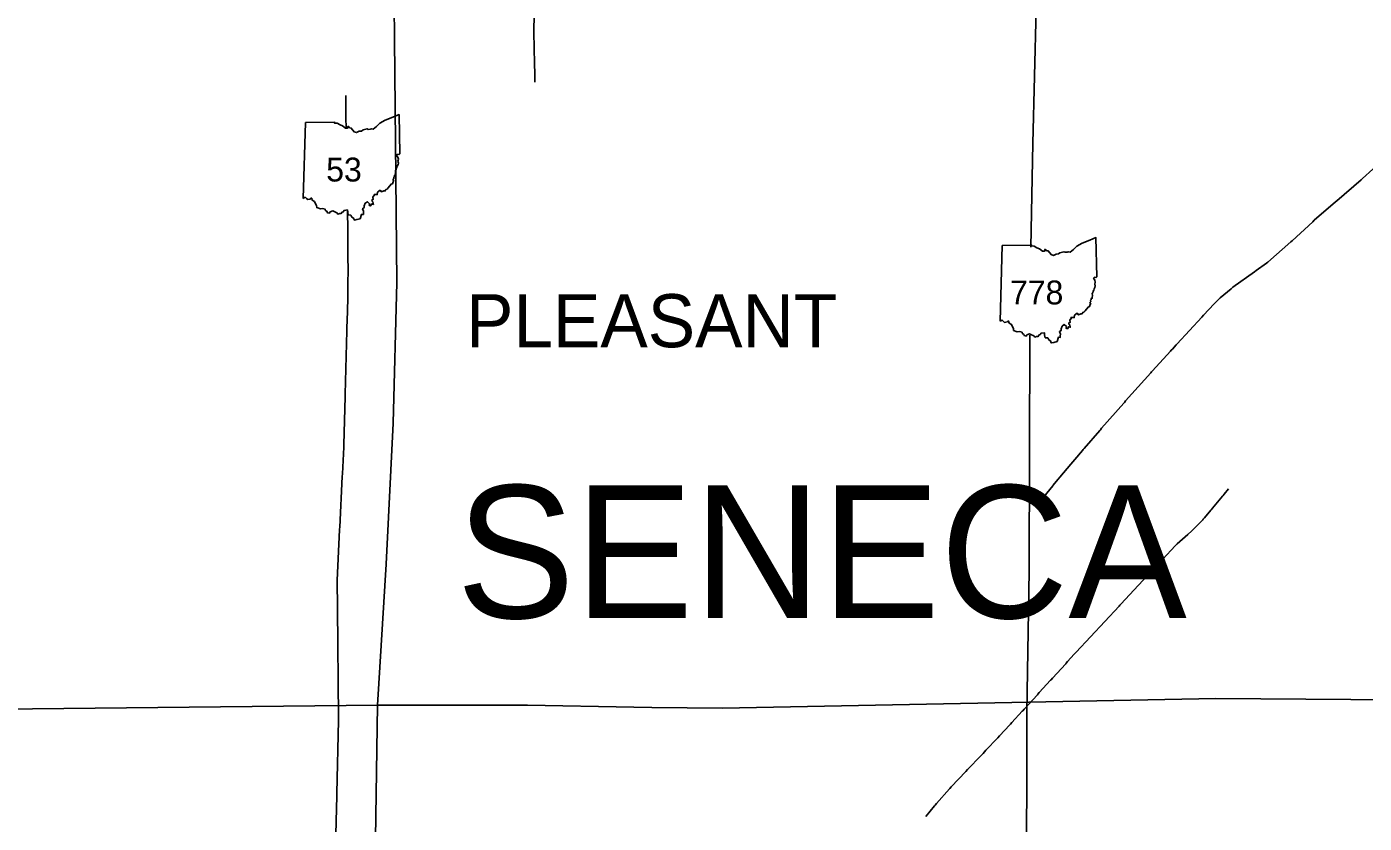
# Model space of a CAD drawing. Extents: x -232 to 448, y 619 to 1059.
# Drawn here: x 257.8 to 309.5, y 743.5 to 774.3 of the extents above; entities that cross this region are included whole.
import ezdxf

# ---------------------------------------------------------------- set-up
doc = ezdxf.new("R2010")
doc.units = 0
doc.layers.add('Default', color=7, linetype='Continuous')

msp = doc.modelspace()

# ---------------------------------------------------------------- linework, layer by layer
at = {"layer": 'Default'}
for p, q in [((268.493, 767.694), (268.575, 770.623)), ((268.493, 767.694), (268.575, 770.623)), ((295.404, 762.944), (295.485, 765.873)), ((295.404, 762.944), (295.485, 765.873))]:
    msp.add_line(p, q, dxfattribs=at)
for points in [[(277.435, 772.188), (277.432, 772.446), (277.422, 772.97), (277.413, 773.432), (277.399, 774.19), (277.413, 774.769), (277.424, 775.181), (277.447, 775.716), (277.475, 776.402), (277.501, 776.941), (277.52, 777.383), (277.539, 777.843), (277.555, 778.261), (277.567, 778.607), (277.572, 779.098), (277.583, 779.571), (277.604, 780.06), (277.627, 780.618), (277.635, 780.905)], [(296.593, 765.811), (296.668, 769.813), (296.793, 775.026), (297.049, 780.749)], [(271.364, 748.108), (271.69, 753.559), (271.965, 759.004), (272.104, 764.439), (272.061, 769.867), (271.962, 779.188)], [(270.145, 770.404), (270.145, 770.418), (270.142, 770.81), (270.137, 771.343), (270.133, 771.671)], [(268.575, 770.623), (269.712, 770.642), (269.694, 770.606), (269.801, 770.599), (269.915, 770.536), (270.012, 770.497), (270.129, 770.404), (270.2, 770.405), (270.23, 770.481), (270.284, 770.422), (270.348, 770.412), (270.459, 770.272), (270.55, 770.241), (270.659, 770.289), (270.741, 770.297), (270.801, 770.345), (270.957, 770.385), (271.001, 770.361), (271.083, 770.366), (271.125, 770.384), (271.197, 770.368), (271.324, 770.474), (271.454, 770.6), (271.655, 770.718), (271.954, 770.831), (272.192, 770.931), (272.226, 769.411)], [(268.575, 770.623), (269.712, 770.642), (269.694, 770.606), (269.801, 770.599), (269.915, 770.536), (270.012, 770.497), (270.129, 770.404), (270.2, 770.405), (270.23, 770.481), (270.284, 770.422), (270.348, 770.412), (270.459, 770.272), (270.55, 770.241), (270.659, 770.289), (270.741, 770.297), (270.801, 770.345), (270.957, 770.385), (271.001, 770.361), (271.083, 770.366), (271.125, 770.384), (271.197, 770.368), (271.324, 770.474), (271.454, 770.6), (271.655, 770.718), (271.954, 770.831), (272.192, 770.931), (272.226, 769.411)], [(272.226, 769.411), (272.191, 769.39), (272.136, 769.4), (272.1, 769.357), (272.145, 769.286), (272.166, 769.211), (272.147, 769.128), (272.166, 769.06), (272.153, 769.002), (272.119, 768.946), (272.107, 768.891), (272.078, 768.834), (272.081, 768.802), (272.053, 768.777), (272.058, 768.682), (272.044, 768.629), (272.049, 768.584), (272.004, 768.572), (272.014, 768.534), (271.986, 768.505), (271.992, 768.455), (271.959, 768.423), (271.991, 768.36), (271.965, 768.339), (271.944, 768.262), (271.887, 768.246), (271.771, 768.104), (271.73, 768.051), (271.684, 768.037), (271.659, 767.982), (271.603, 767.982), (271.517, 767.944), (271.462, 768.01), (271.366, 767.931), (271.354, 767.839), (271.232, 767.842), (271.237, 767.796), (271.21, 767.782), (271.185, 767.736), (271.199, 767.654), (271.142, 767.633), (271.149, 767.585), (271.186, 767.556), (271.202, 767.465), (271.141, 767.483), (271.091, 767.407), (271.04, 767.425), (271.057, 767.49), (270.97, 767.568), (270.888, 767.505), (270.846, 767.405), (270.845, 767.338), (270.784, 767.297), (270.823, 767.202), (270.816, 767.136), (270.817, 767.074), (270.741, 767.076), (270.695, 766.908)], [(272.226, 769.411), (272.191, 769.39), (272.136, 769.4), (272.1, 769.357), (272.145, 769.286), (272.166, 769.211), (272.147, 769.128), (272.166, 769.06), (272.153, 769.002), (272.119, 768.946), (272.107, 768.891), (272.078, 768.834), (272.081, 768.802), (272.053, 768.777), (272.058, 768.682), (272.044, 768.629), (272.049, 768.584), (272.004, 768.572), (272.014, 768.534), (271.986, 768.505), (271.992, 768.455), (271.959, 768.423), (271.991, 768.36), (271.965, 768.339), (271.944, 768.262), (271.887, 768.246), (271.771, 768.104), (271.73, 768.051), (271.684, 768.037), (271.659, 767.982), (271.603, 767.982), (271.517, 767.944), (271.462, 768.01), (271.366, 767.931), (271.354, 767.839), (271.232, 767.842), (271.237, 767.796), (271.21, 767.782), (271.185, 767.736), (271.199, 767.654), (271.142, 767.633), (271.149, 767.585), (271.186, 767.556), (271.202, 767.465), (271.141, 767.483), (271.091, 767.407), (271.04, 767.425), (271.057, 767.49), (270.97, 767.568), (270.888, 767.505), (270.846, 767.405), (270.845, 767.338), (270.784, 767.297), (270.823, 767.202), (270.816, 767.136), (270.817, 767.074), (270.741, 767.076), (270.695, 766.908)], [(296.922, 755.957), (297.432, 756.587), (297.455, 756.616), (297.501, 756.67), (297.85, 757.082), (297.867, 757.101), (297.92, 757.164), (298.582, 757.948), (298.613, 757.985), (298.652, 758.031), (299.251, 758.726), (299.275, 758.754), (299.322, 758.808), (300.177, 759.783), (300.201, 759.811), (300.248, 759.864), (301.217, 760.954), (301.245, 760.985), (301.29, 761.034), (301.981, 761.793), (302.008, 761.823), (302.054, 761.873), (302.199, 762.032), (302.236, 762.073), (303.19, 763.109), (303.262, 763.187), (303.667, 763.624), (303.704, 763.664), (303.861, 763.813), (303.904, 763.853), (304.318, 764.202), (304.318, 764.202), (304.389, 764.262), (305.23, 764.857), (305.296, 764.904), (305.69, 765.191), (305.736, 765.225), (306.632, 766.01), (306.684, 766.055), (307.475, 766.795), (307.531, 766.847), (308.349, 767.557), (308.399, 767.6), (309.338, 768.418), (309.392, 768.465), (310.198, 769.189)], [(270.695, 766.908), (270.562, 766.876), (270.47, 766.856), (270.438, 766.933), (270.372, 766.973), (270.329, 767.05), (270.234, 767.061), (270.212, 767.166), (270.201, 767.252), (270.072, 767.231), (270.037, 767.178), (269.991, 767.164), (269.964, 767.111), (269.902, 767.107), (269.835, 767.082), (269.791, 767.134), (269.681, 767.186), (269.632, 767.213), (269.528, 767.171), (269.506, 767.122), (269.424, 767.143), (269.405, 767.198), (269.355, 767.215), (269.344, 767.273), (269.238, 767.304), (269.156, 767.292), (269.013, 767.339), (269.004, 767.416), (268.955, 767.509), (268.93, 767.574), (268.839, 767.624), (268.821, 767.701), (268.792, 767.699), (268.765, 767.667), (268.665, 767.653), (268.624, 767.685), (268.568, 767.738), (268.493, 767.694)], [(270.695, 766.908), (270.562, 766.876), (270.47, 766.856), (270.438, 766.933), (270.372, 766.973), (270.329, 767.05), (270.234, 767.061), (270.212, 767.166), (270.201, 767.252), (270.072, 767.231), (270.037, 767.178), (269.991, 767.164), (269.964, 767.111), (269.902, 767.107), (269.835, 767.082), (269.791, 767.134), (269.681, 767.186), (269.632, 767.213), (269.528, 767.171), (269.506, 767.122), (269.424, 767.143), (269.405, 767.198), (269.355, 767.215), (269.344, 767.273), (269.238, 767.304), (269.156, 767.292), (269.013, 767.339), (269.004, 767.416), (268.955, 767.509), (268.93, 767.574), (268.839, 767.624), (268.821, 767.701), (268.792, 767.699), (268.765, 767.667), (268.665, 767.653), (268.624, 767.685), (268.568, 767.738), (268.493, 767.694)], [(269.71, 741.633), (269.793, 744.604), (269.793, 744.612), (269.795, 744.712), (269.852, 747.521), (269.853, 747.576), (269.852, 747.63), (269.812, 751.854), (269.812, 751.873), (269.811, 751.963), (269.806, 752.829), (269.806, 752.871), (269.809, 752.937), (269.897, 754.885), (269.898, 754.916), (269.902, 754.993), (269.998, 756.941), (269.998, 756.944), (270.004, 757.049), (270.063, 758.077), (270.063, 758.079), (270.065, 758.185), (270.109, 760.026), (270.109, 760.042), (270.111, 760.134), (270.173, 762.571), (270.174, 762.597), (270.176, 762.679), (270.197, 763.329), (270.198, 763.332), (270.201, 763.437), (270.213, 763.762), (270.215, 763.816), (270.216, 764.039), (270.219, 764.408), (270.222, 764.916), (270.221, 765.449), (270.217, 766.003), (270.21, 766.605), (270.202, 767.09), (270.199, 767.251)], [(295.485, 765.873), (296.622, 765.892), (296.604, 765.857), (296.711, 765.849), (296.825, 765.787), (296.922, 765.747), (297.039, 765.654), (297.11, 765.655), (297.14, 765.731), (297.194, 765.672), (297.258, 765.662), (297.369, 765.522), (297.46, 765.491), (297.57, 765.539), (297.651, 765.547), (297.711, 765.595), (297.867, 765.635), (297.911, 765.611), (297.993, 765.616), (298.035, 765.634), (298.107, 765.618), (298.234, 765.724), (298.364, 765.85), (298.565, 765.969), (298.865, 766.081), (299.102, 766.181), (299.136, 764.661)], [(295.485, 765.873), (296.622, 765.892), (296.604, 765.857), (296.711, 765.849), (296.825, 765.787), (296.922, 765.747), (297.039, 765.654), (297.11, 765.655), (297.14, 765.731), (297.194, 765.672), (297.258, 765.662), (297.369, 765.522), (297.46, 765.491), (297.57, 765.539), (297.651, 765.547), (297.711, 765.595), (297.867, 765.635), (297.911, 765.611), (297.993, 765.616), (298.035, 765.634), (298.107, 765.618), (298.234, 765.724), (298.364, 765.85), (298.565, 765.969), (298.865, 766.081), (299.102, 766.181), (299.136, 764.661)], [(299.136, 764.661), (299.101, 764.64), (299.046, 764.65), (299.01, 764.607), (299.055, 764.536), (299.076, 764.461), (299.058, 764.378), (299.076, 764.31), (299.064, 764.253), (299.029, 764.196), (299.017, 764.142), (298.988, 764.084), (298.991, 764.052), (298.963, 764.027), (298.968, 763.932), (298.954, 763.879), (298.959, 763.834), (298.914, 763.822), (298.924, 763.784), (298.896, 763.755), (298.902, 763.705), (298.869, 763.674), (298.901, 763.61), (298.875, 763.59), (298.854, 763.512), (298.797, 763.496), (298.681, 763.355), (298.64, 763.301), (298.595, 763.288), (298.569, 763.232), (298.513, 763.232), (298.428, 763.194), (298.372, 763.26), (298.276, 763.181), (298.265, 763.089), (298.142, 763.092), (298.147, 763.046), (298.12, 763.033), (298.095, 762.986), (298.109, 762.904), (298.052, 762.883), (298.059, 762.836), (298.096, 762.806), (298.112, 762.715), (298.051, 762.734), (298.001, 762.657), (297.95, 762.675), (297.967, 762.74), (297.88, 762.818), (297.798, 762.756), (297.756, 762.655), (297.755, 762.588), (297.694, 762.547), (297.733, 762.452), (297.726, 762.386), (297.727, 762.324), (297.651, 762.326), (297.605, 762.158)], [(299.136, 764.661), (299.101, 764.64), (299.046, 764.65), (299.01, 764.607), (299.055, 764.536), (299.076, 764.461), (299.058, 764.378), (299.076, 764.31), (299.064, 764.253), (299.029, 764.196), (299.017, 764.142), (298.988, 764.084), (298.991, 764.052), (298.963, 764.027), (298.968, 763.932), (298.954, 763.879), (298.959, 763.834), (298.914, 763.822), (298.924, 763.784), (298.896, 763.755), (298.902, 763.705), (298.869, 763.674), (298.901, 763.61), (298.875, 763.59), (298.854, 763.512), (298.797, 763.496), (298.681, 763.355), (298.64, 763.301), (298.595, 763.288), (298.569, 763.232), (298.513, 763.232), (298.428, 763.194), (298.372, 763.26), (298.276, 763.181), (298.265, 763.089), (298.142, 763.092), (298.147, 763.046), (298.12, 763.033), (298.095, 762.986), (298.109, 762.904), (298.052, 762.883), (298.059, 762.836), (298.096, 762.806), (298.112, 762.715), (298.051, 762.734), (298.001, 762.657), (297.95, 762.675), (297.967, 762.74), (297.88, 762.818), (297.798, 762.756), (297.756, 762.655), (297.755, 762.588), (297.694, 762.547), (297.733, 762.452), (297.726, 762.386), (297.727, 762.324), (297.651, 762.326), (297.605, 762.158)], [(297.605, 762.158), (297.472, 762.126), (297.38, 762.107), (297.348, 762.183), (297.282, 762.223), (297.239, 762.3), (297.144, 762.311), (297.122, 762.416), (297.112, 762.502), (296.982, 762.481), (296.947, 762.428), (296.901, 762.414), (296.874, 762.362), (296.812, 762.357), (296.745, 762.332), (296.701, 762.384), (296.591, 762.436), (296.542, 762.463), (296.438, 762.421), (296.416, 762.372), (296.334, 762.394), (296.315, 762.449), (296.265, 762.465), (296.254, 762.523), (296.148, 762.555), (296.067, 762.542), (295.923, 762.589), (295.914, 762.666), (295.865, 762.759), (295.84, 762.824), (295.749, 762.874), (295.731, 762.951), (295.702, 762.949), (295.675, 762.918), (295.575, 762.903), (295.534, 762.935), (295.478, 762.989), (295.404, 762.944)], [(297.605, 762.158), (297.472, 762.126), (297.38, 762.107), (297.348, 762.183), (297.282, 762.223), (297.239, 762.3), (297.144, 762.311), (297.122, 762.416), (297.112, 762.502), (296.982, 762.481), (296.947, 762.428), (296.901, 762.414), (296.874, 762.362), (296.812, 762.357), (296.745, 762.332), (296.701, 762.384), (296.591, 762.436), (296.542, 762.463), (296.438, 762.421), (296.416, 762.372), (296.334, 762.394), (296.315, 762.449), (296.265, 762.465), (296.254, 762.523), (296.148, 762.555), (296.067, 762.542), (295.923, 762.589), (295.914, 762.666), (295.865, 762.759), (295.84, 762.824), (295.749, 762.874), (295.731, 762.951), (295.702, 762.949), (295.675, 762.918), (295.575, 762.903), (295.534, 762.935), (295.478, 762.989), (295.404, 762.944)], [(296.431, 747.845), (296.528, 753.298), (296.556, 762.402)], [(302.646, 754.701), (302.807, 754.844), (302.824, 754.859), (302.884, 754.92), (303.225, 755.267), (303.249, 755.292), (303.296, 755.348), (303.537, 755.639), (303.566, 755.675), (303.606, 755.723), (303.985, 756.18), (304.016, 756.217), (304.053, 756.264), (304.223, 756.474)], [(301.686, 753.753), (302.163, 754.268), (302.191, 754.297), (302.241, 754.342), (302.646, 754.701)], [(294.857, 746.365), (295.302, 746.838), (295.309, 746.846), (295.376, 746.917), (295.782, 747.354), (295.801, 747.374), (295.855, 747.433), (296.256, 747.873), (296.274, 747.892), (296.329, 747.953), (296.841, 748.512), (296.856, 748.528), (296.915, 748.592), (297.354, 749.07), (297.37, 749.087), (297.427, 749.15), (297.937, 749.711), (297.954, 749.731), (298.009, 749.792), (298.26, 750.075), (298.298, 750.117), (298.334, 750.157), (299.996, 751.931), (300.031, 751.97), (300.069, 752.01), (301.429, 753.476), (301.45, 753.499), (301.502, 753.555), (301.686, 753.753)], [(271.364, 748.108), (277.155, 748.106), (281.265, 748.03), (281.95, 748.017), (284.681, 747.994), (303.733, 748.362)], [(303.733, 748.362), (336.743, 748.122)], [(238.85, 748.082), (244.144, 747.953), (249.543, 747.875), (271.364, 748.108)], [(271.364, 748.108), (270.866, 715.498)], [(296.431, 747.845), (296.414, 732.879)], [(292.528, 743.801), (292.87, 744.221), (292.893, 744.249), (292.94, 744.303), (293.444, 744.87), (293.46, 744.889), (293.517, 744.949), (294.075, 745.54), (294.079, 745.544), (294.149, 745.618), (294.672, 746.168), (294.703, 746.2), (294.746, 746.246), (294.857, 746.365)]]:
    msp.add_lwpolyline(points, dxfattribs=at)

# ---------------------------------------------------------------- texts
for s, height, p in [('53', 0.9234, (269.379, 768.347)), ('778', 0.9234, (295.784, 763.597)), ('PLEASANT', 2.052, (274.779, 761.941)), ('SENECA', 5.13, (274.403, 751.473))]:
    msp.add_text(s, height=height, dxfattribs=at).set_placement(p)

doc.saveas('drawing.dxf')
